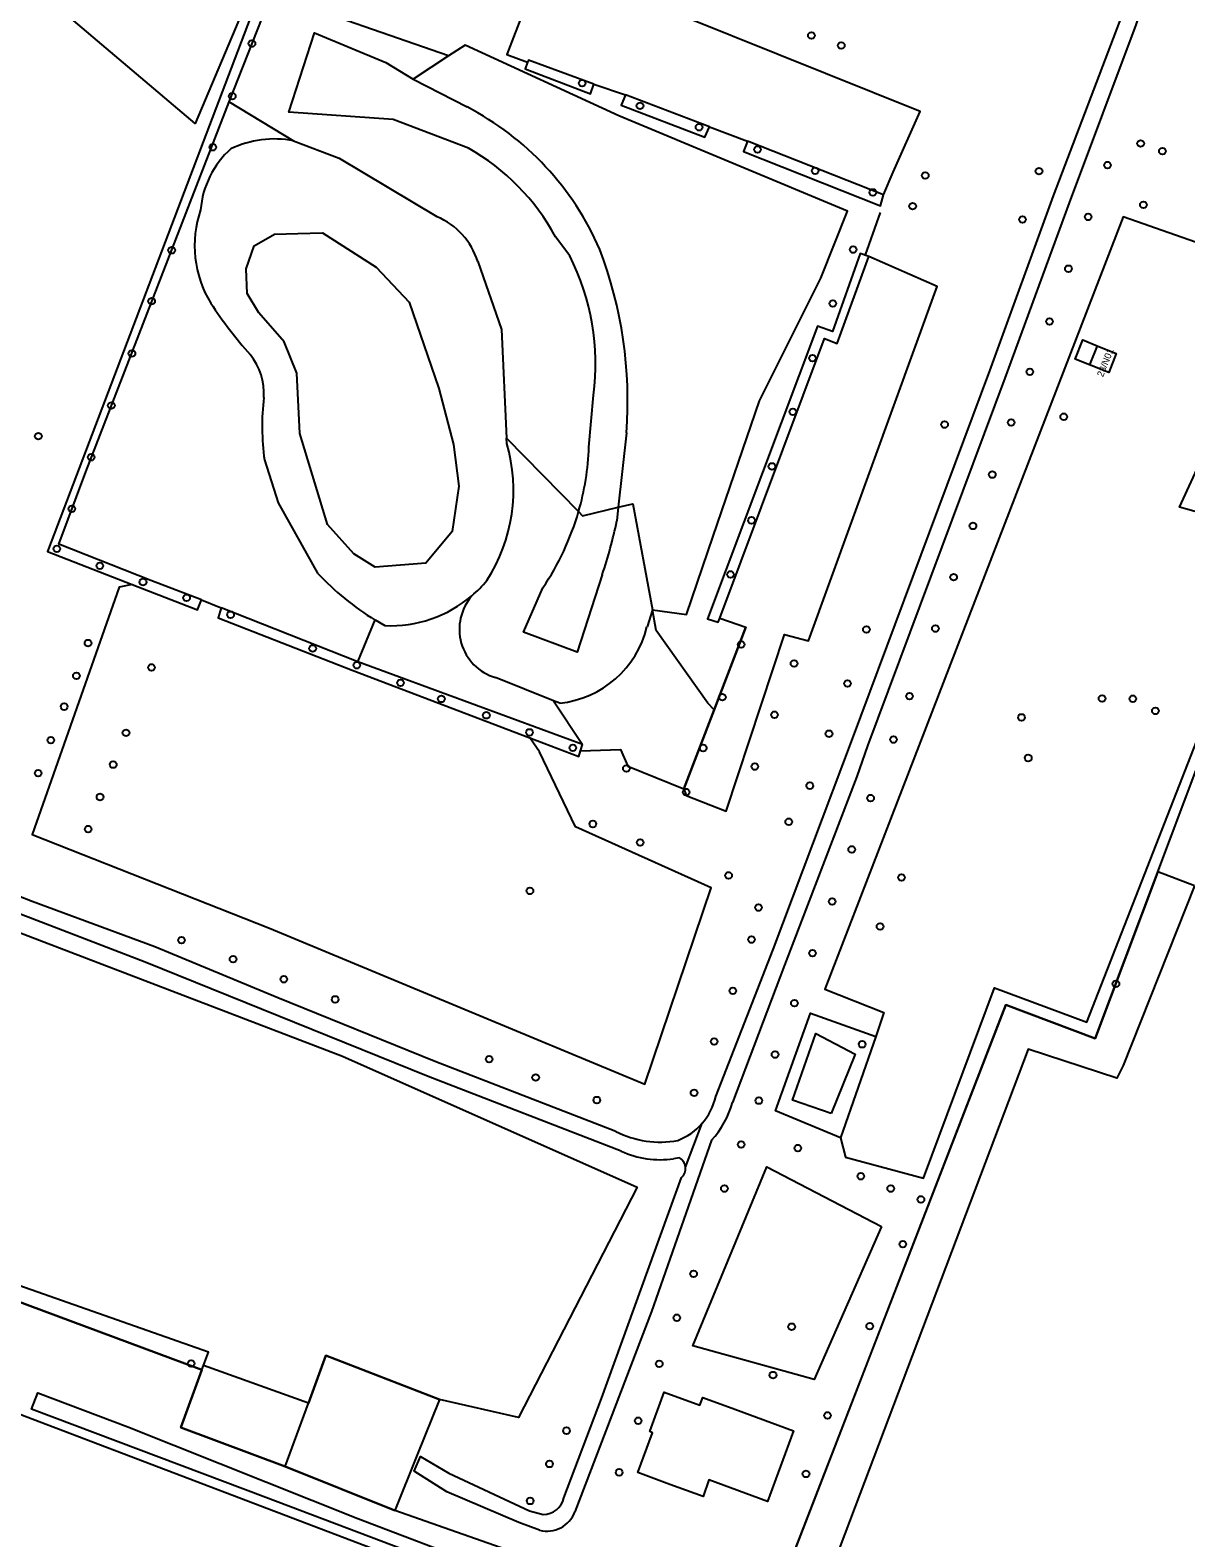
# Model space of a CAD drawing. Extents: x 155209 to 156823, y 385356 to 388482.
# Drawn here: x 155484.9 to 155653.4, y 386517.4 to 386737.4 of the extents above; entities that cross this region are included whole.
import ezdxf

# ---------------------------------------------------------------- set-up
doc = ezdxf.new("R2010")
doc.units = 0
for name, color, linetype in [('IMGEO_Boom', 7, 'Continuous'), ('IMGEO_Bouwland', 7, 'Continuous'), ('IMGEO_Gemengd_bos', 7, 'Continuous'), ('IMGEO_Groenvoorziening', 7, 'Continuous'), ('IMGEO_Haag', 7, 'Continuous'), ('IMGEO_Hek', 7, 'Continuous'), ('IMGEO_Houtwal', 7, 'Continuous'), ('IMGEO_Loofbos', 7, 'Continuous'), ('IMGEO_Meer_plas_ven_vijver', 7, 'Continuous'), ('IMGEO_Pand', 7, 'Continuous'), ('IMGEO_Pand_nummerreeks', 7, 'Continuous'), ('IMGEO_Rijbaan_lokaal_halfverhard', 7, 'Continuous'), ('IMGEO_Rijbaan_lokaal_onverhard', 7, 'Continuous')]:
    doc.layers.add(name, color=color, linetype=linetype)

msp = doc.modelspace()

# ---------------------------------------------------------------- linework, layer by layer
at = {"layer": 'IMGEO_Boom'}
for centre in [(155598.82, 386736.66), (155517.21, 386735.47), (155603.18, 386735.18), (155565.39, 386729.7), (155514.34, 386727.79), (155573.82, 386726.38), (155582.43, 386723.26), (155511.51, 386720.34), (155646.85, 386720.9), (155590.95, 386720.03), (155650.02, 386719.78), (155599.37, 386716.9), (155615.43, 386716.21), (155632.02, 386716.86), (155642.02, 386717.74), (155607.8, 386713.76), (155613.59, 386711.74), (155647.25, 386711.94), (155629.61, 386709.79), (155639.2, 386710.17), (155505.5, 386705.31), (155604.91, 386705.41), (155636.31, 386702.62), (155502.58, 386697.89), (155601.95, 386697.55), (155633.55, 386694.91), (155499.71, 386690.24), (155598.98, 386689.56), (155630.68, 386687.56), (155496.7, 386682.66), (155596.11, 386681.73), (155635.63, 386681.02), (155618.25, 386679.87), (155627.95, 386680.18), (155486.05, 386678.18), (155493.75, 386675.1), (155593.07, 386673.77), (155625.21, 386672.57), (155490.93, 386667.58), (155590.1, 386665.9), (155622.39, 386665.08), (155488.75, 386661.74), (155495.02, 386659.27), (155501.32, 386656.9), (155587.01, 386658.01), (155619.57, 386657.61), (155507.68, 386654.61), (155514.1, 386652.13), (155606.84, 386649.97), (155616.91, 386650.1), (155493.3, 386647.99), (155588.58, 386647.8), (155526.07, 386647.21), (155502.56, 386644.44), (155532.52, 386644.75), (155596.29, 386645.01), (155491.6, 386643.21), (155538.87, 386642.19), (155604.08, 386642.1), (155544.84, 386639.84), (155585.83, 386640.09), (155613.12, 386640.24), (155641.22, 386639.91), (155645.71, 386639.87), (155489.83, 386638.71), (155551.4, 386637.45), (155593.43, 386637.53), (155629.46, 386637.15), (155649, 386638.09), (155498.84, 386634.88), (155557.7, 386634.96), (155601.39, 386634.76), (155487.88, 386633.82), (155564.02, 386632.71), (155583.05, 386632.68), (155610.79, 386633.9), (155496.98, 386630.25), (155630.46, 386631.22), (155486.02, 386629.01), (155571.83, 386629.68), (155590.57, 386629.96), (155580.55, 386626.25), (155598.58, 386627.18), (155495.05, 386625.53), (155607.46, 386625.37), (155566.93, 386621.59), (155595.51, 386621.92), (155493.33, 386620.85), (155573.84, 386618.88), (155604.7, 386617.88), (155586.74, 386614.09), (155611.97, 386613.79), (155557.76, 386611.82), (155591.11, 386609.39), (155601.86, 386610.29), (155608.84, 386606.64), (155506.94, 386604.64), (155590.08, 386604.72), (155514.46, 386601.87), (155598.99, 386602.74), (155521.86, 386598.93), (155587.36, 386597.24), (155643.24, 386598.27), (155529.34, 386596), (155596.34, 386595.45), (155584.64, 386589.86), (155606.22, 386589.44), (155551.81, 386587.28), (155593.52, 386587.94), (155558.6, 386584.59), (155581.7, 386582.35), (155567.52, 386581.31), (155591.15, 386581.22), (155588.58, 386574.82), (155596.83, 386574.3), (155606.02, 386570.18), (155586.13, 386568.38), (155610.39, 386568.38), (155614.8, 386566.81), (155612.16, 386560.28), (155581.64, 386555.95), (155579.2, 386549.54), (155595.94, 386548.23), (155607.33, 386548.32), (155508.35, 386542.86), (155576.63, 386542.82), (155593.22, 386541.18), (155573.56, 386534.51), (155601.16, 386535.29), (155563.1, 386533.06), (155560.6, 386528.2), (155570.78, 386526.98), (155598.03, 386526.75), (155557.8, 386522.8)]:
    msp.add_circle(centre, 0.489, dxfattribs=at)
at = {"layer": 'IMGEO_Bouwland'}
msp.add_lwpolyline([(155432.98, 386515.43), (155442.51, 386540.4), (155458.03, 386534.5), (155472.46, 386539.61), (155681.76, 386459.92), (155721.49, 386444.64), (155766.18, 386427.43)], dxfattribs=at)
at = {"layer": 'IMGEO_Gemengd_bos'}
for points in [[(155502.98, 386770.15), (155524.05, 386759.67), (155508.92, 386723.82), (155488.64, 386740.97)], [(155609.34, 386713.39), (155610.76, 386716.71), (155614.71, 386725.57), (155559.71, 386747.69), (155554.38, 386733.89), (155557.42, 386732.74)], [(155575.62, 386652.84), (155580.62, 386652.16), (155584.5, 386663.6), (155591.24, 386683.36), (155600.2, 386701.22), (155604.08, 386711.01), (155570.71, 386724.93), (155548.3, 386735.23), (155545.88, 386733.7)], [(155567.07, 386729.53), (155571.68, 386727.98)], [(155583.96, 386723.33), (155589.49, 386721.25)], [(155580.19, 386626.71), (155580.55, 386625.76), (155586.4, 386623.44), (155594.89, 386649.26), (155598.42, 386648.34), (155617.16, 386700), (155607.21, 386704.4)], [(155570.65, 386667.82), (155572.79, 386668.33), (155575.62, 386652.84)], [(155499.74, 386656.54), (155497.83, 386656.14), (155485.14, 386620.07), (155519.77, 386606.37), (155574.54, 386583.62), (155584.21, 386612.25), (155564.4, 386621.18), (155559.17, 386632.13), (155557.77, 386634.17)], [(155584.63, 386638.24), (155583.73, 386639.23), (155576.18, 386649.81), (155575.62, 386652.84)], [(155585.46, 386651.62), (155589.27, 386650.29), (155584.63, 386638.24)], [(155565.14, 386632.28), (155570.97, 386632.44), (155572.02, 386630.03), (155580.19, 386626.71)]]:
    msp.add_lwpolyline(points, dxfattribs=at)
at = {"layer": 'IMGEO_Groenvoorziening'}
for points in [[(155554.4, 386677.12), (155554.36, 386677.91)], [(155519.02, 386674.72), (155521.02, 386668.47), (155526.79, 386658.21)], [(155570.65, 386667.82), (155570.43, 386665.81)], [(155568.3, 386657.96), (155564.65, 386646.65), (155556.83, 386649.59), (155559.66, 386656.05)], [(155509.85, 386654.32), (155512.7, 386653.15)], [(155575.62, 386652.84), (155574.84, 386650.36)], [(155532.68, 386645.23), (155535.18, 386651.36)], [(155535.18, 386651.36), (155536.61, 386650.53)], [(155649.36, 386614.6), (155661.74, 386647.58)], [(155561.2, 386639.58), (155552.72, 386642.95)], [(155561.2, 386639.58), (155565.45, 386633.21)], [(155562.12, 386639.22), (155561.2, 386639.58)], [(155584.63, 386638.24), (155580.19, 386626.71)], [(155510.15, 386542.56), (155510.87, 386544.51), (155444.84, 386567.72), (155460.17, 386609.32), (155463.57, 386613.3), (155530.42, 386587.71), (155573.42, 386568.6), (155556.11, 386534.98), (155544.59, 386537.6)], [(155603.06, 386575.78), (155593.6, 386579.74), (155598.69, 386593.98), (155608.22, 386590.58)], [(155601.7, 386579.32), (155596.04, 386581.28), (155599.46, 386591.03), (155605.19, 386588), (155601.7, 386579.32)], [(155509.92, 386541.92), (155450.91, 386563.89), (155449.31, 386562.51), (155445.36, 386559.08), (155429.65, 386517.46)], [(155544.59, 386537.6), (155527.99, 386544.04), (155525.45, 386537.09)], [(155522.08, 386527.84), (155506.85, 386533.54), (155509.92, 386541.92)], [(155509.92, 386541.92), (155510.15, 386542.56)], [(155525.45, 386537.09), (155510.15, 386542.56)], [(155522.08, 386527.84), (155525.45, 386537.09)], [(155544.59, 386537.6), (155541.33, 386529.53), (155538.05, 386521.42)], [(155538.05, 386521.42), (155522.08, 386527.84)], [(155591.34, 386502.7), (155538.05, 386521.42)]]:
    msp.add_lwpolyline(points, dxfattribs=at)
for centre, radius, start, end in [((155520.48, 386706.9), 14.65, 79.0403, 115.6529), ((155523.05, 386710.15), 13.37, 131.7858, 175.4859), ((155525.02, 386705.97), 16.17, 161.1281, 211.2567), ((155567.03, 386734.46), 66.91, 213.4524, 221.5404), ((155510.03, 386684.44), 8.93, 356.0961, 39.2171), ((155556.42, 386679.63), 37.72, 173.6046, 187.4889), ((155530.83, 386670.33), 24.53, 327.3618, 16.0656), ((155526.9, 386678.13), 39.5, 326.0222, 343.8961), ((155498.28, 386681.19), 73.78, 341.6442, 347.9678), ((155555.47, 386684.79), 39.11, 222.8249, 238.7488), ((155537.49, 386668.8), 18.24, 310.3425, 320.1013), ((155537.4, 386668.87), 18.35, 267.5225, 310.4059), ((155554.85, 386650.02), 7.38, 138.6882, 253.2457), ((155560.57, 386653.82), 14.68, 276.0714, 346.3954)]:
    msp.add_arc(centre, radius, start, end, dxfattribs=at)
at = {"layer": 'IMGEO_Haag'}
for points in [[(155520.05, 386742.67), (155526.72, 386759.39), (155524.86, 386760.1), (155487.37, 386661.36), (155499.74, 386656.54)], [(155513.88, 386726.96), (155520.05, 386742.67)], [(155557.42, 386732.74), (155557.06, 386731.77), (155566.62, 386728.16), (155567.07, 386729.53)], [(155567.07, 386729.53), (155557.55, 386733.04), (155557.42, 386732.74)], [(155571.68, 386727.98), (155571.06, 386726.49), (155583.26, 386721.79), (155583.96, 386723.33)], [(155583.96, 386723.33), (155571.68, 386727.98)], [(155509.85, 386654.32), (155502.46, 386657.1), (155489.03, 386662.42), (155492.99, 386672.97), (155513.88, 386726.96)], [(155589.49, 386721.25), (155588.92, 386719.73), (155608.88, 386711.8), (155609.34, 386713.39)], [(155609.34, 386713.39), (155589.49, 386721.25)], [(155607.21, 386704.4), (155605.92, 386704.82), (155601.92, 386693.45), (155599.71, 386694.23), (155583.65, 386651.53), (155585.21, 386651.06), (155585.46, 386651.62)], [(155585.46, 386651.62), (155600.73, 386692.44), (155602.58, 386691.71), (155607.21, 386704.4)], [(155499.74, 386656.54), (155509.27, 386652.83), (155509.85, 386654.32)], [(155512.7, 386653.15), (155512.27, 386651.66), (155531.83, 386644.04), (155557.77, 386634.17)], [(155532.68, 386645.23), (155512.7, 386653.15)], [(155565.45, 386633.21), (155532.68, 386645.23)], [(155557.77, 386634.17), (155564.88, 386631.43), (155565.14, 386632.28)], [(155565.14, 386632.28), (155565.45, 386633.21)]]:
    msp.add_lwpolyline(points, dxfattribs=at)
at = {"layer": 'IMGEO_Hek'}
for points in [[(155608.83, 386710.8), (155606.67, 386704.64)], [(155639.41, 386688.59), (155637.32, 386689.42), (155638.4, 386692.22), (155640.49, 386691.38)], [(155584.63, 386638.24), (155589.27, 386650.29)], [(155640.23, 386590.29), (155661.74, 386647.58)], [(155580.19, 386626.71), (155584.63, 386638.24)], [(155570.97, 386632.44), (155572.02, 386630.03), (155580.19, 386626.71)], [(155592, 386504.11), (155627.17, 386595.2)], [(155627.17, 386595.2), (155640.23, 386590.29)], [(155449.31, 386562.51), (155450.91, 386563.89), (155509.92, 386541.92)], [(155510.15, 386542.56), (155510.87, 386544.51)], [(155525.45, 386537.09), (155527.99, 386544.04), (155544.59, 386537.6)], [(155509.92, 386541.92), (155506.85, 386533.54), (155522.08, 386527.84)], [(155509.92, 386541.92), (155510.15, 386542.56)], [(155522.08, 386527.84), (155525.45, 386537.09)], [(155544.59, 386537.6), (155541.33, 386529.53)], [(155541.33, 386529.53), (155538.05, 386521.42)], [(155522.08, 386527.84), (155538.05, 386521.42)]]:
    msp.add_lwpolyline(points, dxfattribs=at)
at = {"layer": 'IMGEO_Houtwal'}
for points in [[(155649.36, 386614.6), (155640.23, 386590.29), (155627.17, 386595.2), (155591.34, 386502.7)], [(155654.71, 386612.58), (155649.36, 386614.6)], [(155654.71, 386612.58), (155644.31, 386586.34), (155643.39, 386584.49), (155630.42, 386588.72), (155597.41, 386501.42)]]:
    msp.add_lwpolyline(points, dxfattribs=at)
at = {"layer": 'IMGEO_Loofbos'}
for points in [[(155545.88, 386733.7), (155520.05, 386742.67)], [(155548.78, 386720.2), (155537.79, 386724.39), (155522.61, 386725.48), (155526.36, 386737.05), (155536.74, 386732.73), (155540.72, 386730.27)], [(155545.88, 386733.7), (155540.72, 386730.27)], [(155540.72, 386730.27), (155548.59, 386726.23)], [(155513.88, 386726.96), (155523.27, 386721.29)], [(155523.27, 386721.29), (155529.95, 386718.75), (155544.18, 386710.22)], [(155603.06, 386575.78), (155603.8, 386572.97), (155615.16, 386569.9), (155625.52, 386597.7), (155639.02, 386592.67), (155666.82, 386663.83), (155652.54, 386667.82), (155668.19, 386701.83), (155644.3, 386710.17), (155600.79, 386597.51), (155609.41, 386594.06), (155608.22, 386590.58)], [(155563.56, 386704.49), (155561.49, 386707.28)], [(155550.15, 386703.67), (155553.62, 386693.77), (155554.36, 386677.91)], [(155639.41, 386688.59), (155637.32, 386689.42), (155638.4, 386692.22), (155640.49, 386691.38)], [(155566.37, 386676.6), (155567.02, 386684.18)], [(155554.36, 386677.91), (155564.85, 386667.17)], [(155571.83, 386678.68), (155570.65, 386667.82)], [(155564.85, 386667.17), (155565.43, 386666.57), (155570.65, 386667.82)], [(155608.22, 386590.58), (155603.06, 386575.78)], [(155609.06, 386562.84), (155599.22, 386540.54), (155581.52, 386545.43), (155592.32, 386571.58), (155609.06, 386562.84)]]:
    msp.add_lwpolyline(points, dxfattribs=at)
for centre, radius, start, end in [((155528.8, 386688.4), 42.7, 23.5165, 62.3943), ((155532.6, 386691.57), 32.89, 28.5423, 60.5139), ((155540.24, 386700.63), 10.36, 17.0366, 67.6466), ((155509.69, 386683.33), 62.32, 355.7271, 20.7754), ((155532.42, 386688.74), 34.9, 352.4872, 26.8297), ((155526.99, 386678.1), 39.41, 343.9004, 357.8143)]:
    msp.add_arc(centre, radius, start, end, dxfattribs=at)
at = {"layer": 'IMGEO_Meer_plas_ven_vijver'}
msp.add_lwpolyline([(155523.89, 386707.77), (155527.52, 386707.84), (155535.34, 386702.85), (155540.14, 386697.76), (155544.49, 386685.14), (155546.62, 386676.98), (155547.41, 386670.91), (155546.43, 386664.27), (155542.58, 386659.66), (155535.21, 386659.09), (155532.06, 386661.02), (155528.25, 386665.27), (155524.18, 386678.55), (155523.74, 386687.38), (155521.89, 386691.96), (155518.24, 386696.19), (155516.52, 386698.98), (155516.38, 386702.58), (155517.55, 386705.98), (155520.51, 386707.68), (155523.89, 386707.77)], dxfattribs=at)
at = {"layer": 'IMGEO_Pand'}
for points in [[(155640.49, 386691.38), (155639.41, 386688.59)], [(155640.49, 386691.38), (155643.29, 386690.26), (155642.19, 386687.48), (155639.41, 386688.59)], [(155578.19, 386525.22), (155573.5, 386526.95), (155575.62, 386532.76), (155575.23, 386532.93), (155577.36, 386538.68), (155582.53, 386536.77), (155582.96, 386537.91), (155587.65, 386536.19), (155596.2, 386533.05), (155592.43, 386522.74), (155583.87, 386525.88), (155583.01, 386523.45), (155578.19, 386525.22)]]:
    msp.add_lwpolyline(points, dxfattribs=at)
at = {"layer": 'IMGEO_Rijbaan_lokaal_halfverhard'}
for points in [[(155650.78, 386752.11), (155646.13, 386738.19), (155636.4, 386712.24), (155627.03, 386686.65), (155606.99, 386633), (155605.46, 386628.53), (155594.88, 386600.99), (155587.3, 386580.96)], [(155584.86, 386581.8), (155593.26, 386603.28), (155604.83, 386634.04), (155624.86, 386687.72), (155634.14, 386713.25), (155644.18, 386739.73), (155644.34, 386740.74)], [(155570.3, 386576.72), (155543.8, 386587), (155521, 386596.24), (155503.05, 386603.65), (155485.17, 386610.28), (155467.59, 386617.16), (155457.92, 386621.1)], [(155571.09, 386573.85), (155542.93, 386584.75), (155501.65, 386601.44), (155467.05, 386614.69), (155464.68, 386615.53)], [(155580.45, 386571.52), (155582.89, 386577.91)], [(155584.25, 386575.44), (155575.49, 386550.45), (155564.31, 386521.2)], [(155579.57, 386572.89), (155578.69, 386572.74)], [(155562.7, 386523.24), (155568.22, 386537.74), (155579.86, 386569.99)], [(155559.18, 386518.54), (155556.16, 386519.64), (155545.65, 386524.12), (155540.88, 386527.15), (155541.78, 386529.29), (155545.94, 386526.86), (155557.69, 386521.35), (155559.7, 386520.84)]]:
    msp.add_lwpolyline(points, dxfattribs=at)
for centre, radius, start, end in [((155576.18, 386583.75), 8.9, 319.0086, 347.3435), ((155574.23, 386584.59), 13.57, 317.5884, 344.4595), ((155576.17, 386583.75), 8.9, 290.7115, 319.0333), ((155576.72, 386589.36), 14.18, 243.0702, 280.5647), ((155576.74, 386585.88), 13.28, 244.8173, 278.4331), ((155578.65, 386571.34), 1.81, 5.7421, 59.3781), ((155578.66, 386571.33), 1.8, 311.9914, 5.7621), ((155559.73, 386523.87), 3.03, 269.4259, 348.1126), ((155560.25, 386522.76), 4.36, 255.7681, 339.0177)]:
    msp.add_arc(centre, radius, start, end, dxfattribs=at)
at = {"layer": 'IMGEO_Rijbaan_lokaal_onverhard'}
msp.add_lwpolyline([(155766.18, 386427.43), (155744.69, 386436.76), (155676.9, 386462.65), (155615.15, 386486.99), (155519.22, 386523.29), (155485.06, 386536.21), (155485.96, 386538.58), (155499.09, 386533.61), (155532.67, 386520.24), (155577.27, 386503.26), (155595.61, 386496.28), (155619.05, 386487.36), (155657.31, 386472.8), (155670.87, 386467.64), (155673.01, 386467.83), (155675.09, 386468.61)], dxfattribs=at)

# ---------------------------------------------------------------- texts
at = {"layer": 'IMGEO_Pand_nummerreeks'}
msp.add_text('23/N01', height=1, rotation=68.5544, dxfattribs=at).set_placement((155641.36, 386686.74))

doc.saveas('drawing.dxf')
